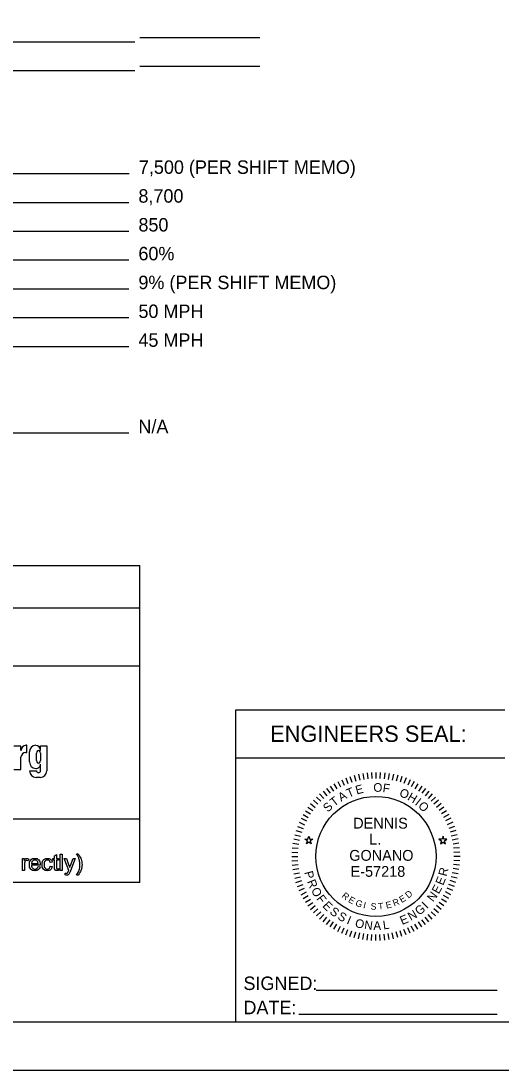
# Model space of a CAD drawing. Extents: x 421.3 to 469.3, y 221.6 to 248.2.
# Drawn here: x 428.32 to 433.32, y 221.63 to 232.55 of the extents above; entities that cross this region are included whole.
import ezdxf

# ---------------------------------------------------------------- set-up
doc = ezdxf.new("R2010")
doc.units = 0
for name, color, linetype in [('Default', 7, 'Continuous'), ('SH_Border', 7, 'Continuous'), ('SH_Cut_Line', 7, 'Continuous'), ('SH_Data', 7, 'Continuous')]:
    doc.layers.add(name, color=color, linetype=linetype)

msp = doc.modelspace()

# ---------------------------------------------------------------- linework, layer by layer
at = {"layer": 'Default'}
for p, q in [((431.79, 224.696), (431.806, 224.635)), ((431.835, 224.707), (431.848, 224.645)), ((431.88, 224.715), (431.89, 224.653)), ((431.925, 224.721), (431.932, 224.659)), ((431.971, 224.724), (431.974, 224.662)), ((432.017, 224.726), (432.017, 224.663)), ((432.062, 224.724), (432.059, 224.662)), ((432.108, 224.721), (432.102, 224.659)), ((432.153, 224.715), (432.144, 224.653)), ((432.199, 224.707), (432.186, 224.645)), ((432.243, 224.696), (432.227, 224.635)), ((431.54, 224.584), (431.574, 224.532)), ((431.579, 224.608), (431.61, 224.554)), ((431.619, 224.63), (431.648, 224.575)), ((431.661, 224.65), (431.686, 224.593)), ((431.703, 224.668), (431.725, 224.609)), ((431.746, 224.683), (431.766, 224.623)), ((432.287, 224.683), (432.268, 224.623)), ((432.33, 224.668), (432.308, 224.609)), ((432.372, 224.65), (432.347, 224.593)), ((432.414, 224.63), (432.385, 224.575)), ((432.454, 224.608), (432.423, 224.554)), ((432.493, 224.584), (432.459, 224.532)), ((431.398, 224.469), (431.442, 224.425)), ((431.431, 224.501), (431.473, 224.454)), ((431.466, 224.531), (431.505, 224.482)), ((431.502, 224.559), (431.539, 224.508)), ((432.531, 224.559), (432.494, 224.508)), ((432.567, 224.531), (432.528, 224.482)), ((432.602, 224.501), (432.56, 224.454)), ((432.635, 224.469), (432.591, 224.425)), ((431.309, 224.365), (431.359, 224.328)), ((431.337, 224.401), (431.385, 224.362)), ((431.366, 224.436), (431.413, 224.394)), ((432.667, 224.436), (432.62, 224.394)), ((432.697, 224.401), (432.648, 224.362)), ((432.724, 224.365), (432.674, 224.328)), ((431.237, 224.248), (431.293, 224.22)), ((431.259, 224.288), (431.313, 224.257)), ((431.283, 224.327), (431.335, 224.293)), ((432.75, 224.327), (432.698, 224.293)), ((432.774, 224.288), (432.72, 224.257)), ((432.796, 224.248), (432.741, 224.22)), ((431.2, 224.164), (431.258, 224.142)), ((431.217, 224.207), (431.274, 224.181)), ((432.816, 224.207), (432.759, 224.181)), ((432.833, 224.164), (432.775, 224.142)), ((431.161, 224.033), (431.222, 224.02)), ((431.171, 224.077), (431.232, 224.061)), ((431.184, 224.121), (431.244, 224.102)), ((431.303, 224.013), (431.277, 224.031)), ((431.277, 224.031), (431.309, 224.031)), ((431.309, 224.031), (431.319, 224.061)), ((431.319, 224.061), (431.328, 224.031)), ((431.328, 224.031), (431.36, 224.031)), ((431.36, 224.031), (431.334, 224.013)), ((432.705, 224.031), (432.673, 224.031)), ((432.673, 224.031), (432.699, 224.013)), ((432.715, 224.061), (432.705, 224.031)), ((432.724, 224.031), (432.715, 224.061)), ((432.756, 224.031), (432.724, 224.031)), ((432.73, 224.013), (432.756, 224.031)), ((432.849, 224.121), (432.789, 224.102)), ((432.862, 224.077), (432.801, 224.061)), ((432.872, 224.033), (432.811, 224.02)), ((431.146, 223.942), (431.209, 223.936)), ((431.152, 223.988), (431.214, 223.978)), ((431.293, 223.983), (431.303, 224.013)), ((431.319, 224.001), (431.293, 223.983)), ((431.344, 223.983), (431.319, 224.001)), ((431.334, 224.013), (431.344, 223.983)), ((432.699, 224.013), (432.689, 223.983)), ((432.689, 223.983), (432.715, 224.001)), ((432.715, 224.001), (432.74, 223.983)), ((432.74, 223.983), (432.73, 224.013)), ((432.881, 223.988), (432.819, 223.978)), ((432.887, 223.942), (432.825, 223.936)), ((431.142, 223.851), (431.204, 223.851)), ((431.143, 223.896), (431.205, 223.893)), ((432.89, 223.896), (432.828, 223.893)), ((432.892, 223.851), (432.829, 223.851)), ((431.143, 223.805), (431.205, 223.808)), ((431.146, 223.759), (431.209, 223.766)), ((431.152, 223.714), (431.214, 223.724)), ((432.881, 223.714), (432.819, 223.724)), ((432.887, 223.759), (432.825, 223.766)), ((432.89, 223.805), (432.828, 223.808)), ((431.161, 223.669), (431.222, 223.682)), ((431.171, 223.624), (431.232, 223.64)), ((431.184, 223.58), (431.244, 223.6)), ((432.849, 223.58), (432.789, 223.6)), ((432.862, 223.624), (432.801, 223.64)), ((432.872, 223.669), (432.811, 223.682)), ((431.2, 223.537), (431.258, 223.56)), ((431.217, 223.495), (431.274, 223.52)), ((432.816, 223.495), (432.759, 223.52)), ((432.833, 223.537), (432.775, 223.56)), ((431.237, 223.453), (431.293, 223.482)), ((431.259, 223.413), (431.313, 223.444)), ((431.283, 223.374), (431.335, 223.408)), ((431.309, 223.336), (431.359, 223.373)), ((432.724, 223.336), (432.674, 223.373)), ((432.75, 223.374), (432.698, 223.408)), ((432.774, 223.413), (432.72, 223.444)), ((432.796, 223.453), (432.741, 223.482)), ((431.337, 223.3), (431.385, 223.339)), ((431.366, 223.265), (431.413, 223.307)), ((431.398, 223.232), (431.442, 223.276)), ((432.635, 223.232), (432.591, 223.276)), ((432.667, 223.265), (432.62, 223.307)), ((432.697, 223.3), (432.648, 223.339)), ((431.431, 223.2), (431.473, 223.247)), ((431.466, 223.171), (431.505, 223.219)), ((431.502, 223.143), (431.539, 223.193)), ((431.54, 223.117), (431.574, 223.169)), ((432.493, 223.117), (432.459, 223.169)), ((432.531, 223.143), (432.494, 223.193)), ((432.567, 223.171), (432.528, 223.219)), ((432.602, 223.2), (432.56, 223.247)), ((431.579, 223.093), (431.61, 223.147)), ((431.619, 223.071), (431.648, 223.127)), ((431.661, 223.051), (431.686, 223.108)), ((431.703, 223.034), (431.725, 223.092)), ((431.746, 223.019), (431.766, 223.078)), ((431.79, 223.006), (431.806, 223.066)), ((431.835, 222.995), (431.848, 223.056)), ((431.88, 222.986), (431.89, 223.048)), ((432.153, 222.986), (432.144, 223.048)), ((432.199, 222.995), (432.186, 223.056)), ((432.243, 223.006), (432.227, 223.066)), ((432.287, 223.019), (432.268, 223.078)), ((432.33, 223.034), (432.308, 223.092)), ((432.372, 223.051), (432.347, 223.108)), ((432.414, 223.071), (432.385, 223.127)), ((432.454, 223.093), (432.423, 223.147)), ((431.925, 222.98), (431.932, 223.043)), ((431.971, 222.977), (431.974, 223.039)), ((432.017, 222.976), (432.017, 223.038)), ((432.062, 222.977), (432.059, 223.039)), ((432.108, 222.98), (432.102, 223.043))]:
    msp.add_line(p, q, dxfattribs=at)
msp.add_circle((432.017, 223.851), 0.625, dxfattribs=at)
at = {"layer": 'SH_Border'}
msp.add_lwpolyline([(423.308, 243.128), (454.808, 243.128), (454.808, 222.128), (423.308, 222.128)], close=True, dxfattribs=at)
at = {"layer": 'SH_Cut_Line'}
msp.add_lwpolyline([(421.308, 221.628), (455.308, 221.628), (455.308, 243.628), (421.308, 243.628)], close=True, dxfattribs=at)
at = {"layer": 'SH_Data'}
for p, q in [((429.508, 232.326), (426.732, 232.326)), ((430.808, 232.372), (429.558, 232.372)), ((429.508, 232.026), (425.243, 232.026)), ((430.808, 232.072), (429.558, 232.072)), ((429.45, 230.955), (425.881, 230.955)), ((429.445, 230.655), (426.306, 230.655)), ((429.445, 230.355), (426.984, 230.355)), ((429.445, 230.055), (426.679, 230.055)), ((429.445, 229.755), (426.182, 229.755)), ((429.445, 229.455), (425.249, 229.455)), ((429.445, 229.155), (425.159, 229.155)), ((429.445, 228.255), (425.219, 228.255)), ((424.333, 226.879), (429.558, 226.879)), ((429.558, 223.579), (429.558, 226.879)), ((424.333, 226.439), (429.558, 226.439)), ((424.333, 225.834), (429.558, 225.834)), ((430.558, 222.128), (430.558, 225.378)), ((430.558, 225.378), (433.358, 225.378)), ((428.323, 225), (428.25, 225)), ((428.323, 224.953), (428.323, 225)), ((428.372, 224.934), (428.384, 224.934)), ((428.384, 225.008), (428.378, 225.008)), ((428.384, 224.934), (428.384, 225.008)), ((428.412, 224.835), (428.412, 224.939)), ((428.484, 224.849), (428.484, 224.925)), ((428.527, 224.955), (428.527, 225.002)), ((428.527, 225.002), (428.592, 225.002)), ((428.527, 224.925), (428.527, 224.849)), ((428.592, 225.002), (428.592, 224.743)), ((428.323, 224.757), (428.323, 224.884)), ((428.527, 224.743), (428.527, 224.813)), ((430.558, 224.878), (433.358, 224.878)), ((428.25, 224.757), (428.323, 224.757)), ((428.412, 224.743), (428.484, 224.743)), ((428.522, 224.674), (428.482, 224.674)), ((429.558, 224.239), (424.333, 224.239)), ((429.558, 223.579), (424.333, 223.579)), ((431.394, 222.461), (433.279, 222.461)), ((431.215, 222.209), (433.279, 222.209))]:
    msp.add_line(p, q, dxfattribs=at)
for points in [[(428.338, 223.706), (428.338, 223.828), (428.356, 223.828), (428.356, 223.81)], [(428.404, 223.824), (428.397, 223.805)], [(428.67, 223.741), (428.67, 223.812), (428.655, 223.812), (428.655, 223.828), (428.67, 223.828), (428.67, 223.859), (428.691, 223.871), (428.691, 223.828), (428.712, 223.828), (428.712, 223.812), (428.691, 223.812), (428.691, 223.74)], [(428.732, 223.706), (428.732, 223.875), (428.753, 223.875), (428.753, 223.706), (428.732, 223.706)], [(428.82, 223.705), (428.773, 223.828), (428.795, 223.828), (428.821, 223.757)], [(428.838, 223.757), (428.865, 223.828), (428.885, 223.828), (428.839, 223.703)], [(428.902, 223.878), (428.917, 223.878)], [(428.358, 223.77), (428.358, 223.706), (428.338, 223.706)], [(428.523, 223.762), (428.431, 223.762)], [(428.432, 223.779), (428.501, 223.779)], [(428.5, 223.745), (428.522, 223.742)], [(428.647, 223.792), (428.626, 223.789)], [(428.628, 223.75), (428.649, 223.748)], [(428.712, 223.724), (428.715, 223.706)], [(428.784, 223.658), (428.782, 223.678)], [(428.917, 223.656), (428.902, 223.656)]]:
    msp.add_lwpolyline(points, dxfattribs=at)
for centre, radius, start, end in [((428.378, 224.953), 0.0548, 90, 180), ((428.372, 224.884), 0.0493, 90, 180), ((428.48, 224.939), 0.0686, 92.6865, 180), ((428.474, 224.955), 0.0524, 0, 86.9262), ((428.481, 224.835), 0.0692, 180, 265.7132), ((428.48, 224.813), 0.0467, 264.7825, 0), ((428.482, 224.743), 0.0699, 180, 270), ((428.522, 224.743), 0.0699, 270, 0)]:
    msp.add_arc(centre, radius, start, end, dxfattribs=at)
for centre, major_axis, ratio, start_param, end_param in [((428.505, 224.925), (0, 0.0275), 0.777179, 4.712389, 7.853982), ((428.505, 224.849), (0, 0.0275), 0.777179, 1.570796, 4.712389), ((428.505, 224.743), (0.0214, 0), 0.959012, 3.141593, 6.283185)]:
    msp.add_ellipse(centre, major_axis=major_axis, ratio=ratio, start_param=start_param, end_param=end_param, dxfattribs=at)
for points in [[(428.356, 223.81), (428.363, 223.823), (428.369, 223.827), (428.376, 223.831), (428.383, 223.831), (428.393, 223.831), (428.404, 223.824)], [(428.522, 223.742), (428.517, 223.724), (428.503, 223.713), (428.489, 223.703), (428.468, 223.703), (428.441, 223.703), (428.425, 223.719), (428.41, 223.736), (428.41, 223.766), (428.41, 223.797), (428.426, 223.814), (428.441, 223.831), (428.467, 223.831), (428.491, 223.831), (428.507, 223.814), (428.523, 223.798), (428.523, 223.767), (428.523, 223.765), (428.523, 223.762)], [(428.501, 223.779), (428.499, 223.794), (428.493, 223.802), (428.483, 223.814), (428.467, 223.814), (428.453, 223.814), (428.443, 223.804), (428.433, 223.795), (428.432, 223.779)], [(428.649, 223.748), (428.645, 223.727), (428.632, 223.715), (428.618, 223.703), (428.598, 223.703), (428.572, 223.703), (428.557, 223.719), (428.542, 223.736), (428.542, 223.766), (428.542, 223.786), (428.548, 223.801), (428.555, 223.816), (428.568, 223.824), (428.582, 223.831), (428.598, 223.831), (428.618, 223.831), (428.63, 223.821), (428.643, 223.811), (428.647, 223.792)], [(428.626, 223.789), (428.624, 223.801), (428.616, 223.808), (428.609, 223.814), (428.599, 223.814), (428.583, 223.814), (428.573, 223.803), (428.563, 223.791), (428.563, 223.767), (428.563, 223.742), (428.573, 223.731), (428.582, 223.72), (428.597, 223.72), (428.61, 223.72), (428.618, 223.727), (428.626, 223.735), (428.628, 223.75)], [(428.902, 223.656), (428.936, 223.711), (428.936, 223.767), (428.936, 223.788), (428.931, 223.81), (428.927, 223.827), (428.92, 223.843), (428.916, 223.854), (428.902, 223.878)], [(428.917, 223.878), (428.938, 223.849), (428.949, 223.82), (428.958, 223.794), (428.958, 223.767), (428.958, 223.736), (428.946, 223.707), (428.934, 223.677), (428.917, 223.656)], [(428.397, 223.805), (428.389, 223.81), (428.382, 223.81), (428.375, 223.81), (428.369, 223.806), (428.364, 223.801), (428.362, 223.794), (428.358, 223.783), (428.358, 223.77)], [(428.431, 223.762), (428.432, 223.741), (428.442, 223.731), (428.453, 223.72), (428.468, 223.72), (428.48, 223.72), (428.488, 223.726), (428.496, 223.732), (428.5, 223.745)], [(428.715, 223.706), (428.706, 223.704), (428.699, 223.704), (428.688, 223.704), (428.682, 223.707), (428.675, 223.711), (428.673, 223.717), (428.67, 223.723), (428.67, 223.741)], [(428.691, 223.74), (428.691, 223.731), (428.692, 223.729), (428.693, 223.726), (428.696, 223.725), (428.698, 223.723), (428.703, 223.723), (428.706, 223.723), (428.712, 223.724)], [(428.782, 223.678), (428.788, 223.676), (428.793, 223.676), (428.8, 223.676), (428.805, 223.678), (428.809, 223.681), (428.811, 223.685), (428.813, 223.688), (428.818, 223.7), (428.818, 223.702), (428.82, 223.705)], [(428.839, 223.703), (428.831, 223.683), (428.827, 223.676), (428.822, 223.665), (428.814, 223.661), (428.807, 223.656), (428.797, 223.656), (428.791, 223.656), (428.784, 223.658)], [(428.821, 223.757), (428.826, 223.744), (428.83, 223.729), (428.833, 223.743), (428.838, 223.757)]]:
    msp.add_open_spline(points, degree=3, dxfattribs=at)

# ---------------------------------------------------------------- texts
at = {"layer": 'Default'}
for s, height, rotation, p in [('E', 0.09, 15.1518, (431.817, 224.495)), ('F', 0.09, 352.4241, (432.083, 224.522)), ('T', 0.09, 37.8794, (431.582, 224.366)), ('A', 0.09, 30.3035, (431.654, 224.419)), ('T', 0.09, 22.7276, (431.732, 224.462)), ('O', 0.09, 337.2724, (432.253, 224.482)), ('H', 0.09, 329.6965, (432.337, 224.444)), ('S', 0.09, 45.4553, (431.519, 224.306)), ('I', 0.09, 322.1206, (432.416, 224.394)), ('O', 0.09, 134.5447, (432.579, 224.368)), ('DENNIS', 0.1125, 360, (431.78, 224.141)), ('L.', 0.1125, 360, (431.947, 223.974)), ('GONANO', 0.1125, 360, (431.739, 223.806)), ('E-57218', 0.1125, 360, (431.753, 223.639)), ('R', 0.09, 75.7588, (432.751, 223.639)), ('P', 0.09, 284.2412, (431.27, 223.687)), ('R', 0.09, 291.8171, (431.298, 223.59)), ('E', 0.09, 68.1829, (432.716, 223.544)), ('O', 0.09, 299.393, (431.338, 223.499)), ('D', 0.0684, 39.2971, (432.354, 223.411)), ('N', 0.09, 53.0312, (432.612, 223.372)), ('E', 0.09, 60.607, (432.67, 223.454)), ('F', 0.09, 306.9688, (431.393, 223.41)), ('E', 0.09, 314.5447, (431.455, 223.332)), ('R', 0.0684, 320.9386, (431.654, 223.431)), ('E', 0.0684, 329.6451, (431.722, 223.381)), ('G', 0.0684, 338.3516, (431.796, 223.342)), ('I', 0.0684, 347.0581, (431.88, 223.314)), ('E', 0.0684, 13.1776, (432.127, 223.307)), ('R', 0.0684, 21.8841, (432.207, 223.33)), ('E', 0.0684, 30.5906, (432.284, 223.365)), ('I', 0.09, 45.4553, (432.548, 223.302)), ('S', 0.09, 322.1206, (431.528, 223.263)), ('S', 0.09, 329.6965, (431.61, 223.204)), ('S', 0.0684, 355.7646, (431.959, 223.299)), ('T', 0.0684, 4.4711, (432.042, 223.297)), ('N', 0.09, 30.3035, (432.38, 223.179)), ('G', 0.09, 37.8794, (432.466, 223.233)), ('I', 0.09, 337.2724, (431.705, 223.153)), ('O', 0.09, 344.8482, (431.792, 223.12)), ('N', 0.09, 352.4241, (431.891, 223.097)), ('L', 0.09, 7.5759, (432.095, 223.091)), ('E', 0.09, 22.7276, (432.289, 223.137))]:
    msp.add_text(s, height=height, rotation=rotation, dxfattribs=at).set_placement(p)
for s, p in [('O', (431.99, 224.524)), ('A', (431.99, 223.087))]:
    msp.add_text(s, height=0.09, dxfattribs=at).set_placement(p)
at = {"layer": 'SH_Data'}
for s, height, p in [('7,500 (PER SHIFT MEMO)', 0.14, (429.55, 230.955)), ('8,700 ', 0.14, (429.545, 230.655)), ('850   ', 0.14, (429.545, 230.355)), ('60%   ', 0.14, (429.545, 230.055)), ('9% (PER SHIFT MEMO)', 0.14, (429.545, 229.755)), ('50 MPH', 0.14, (429.545, 229.455)), ('45 MPH', 0.14, (429.545, 229.155)), ('N/A   ', 0.14, (429.545, 228.255)), ('ENGINEERS SEAL:', 0.17, (430.915, 225.043)), ('SIGNED:', 0.14, (430.638, 222.461)), ('DATE:', 0.14, (430.638, 222.209))]:
    msp.add_text(s, height=height, dxfattribs=at).set_placement(p)

doc.saveas('drawing.dxf')
